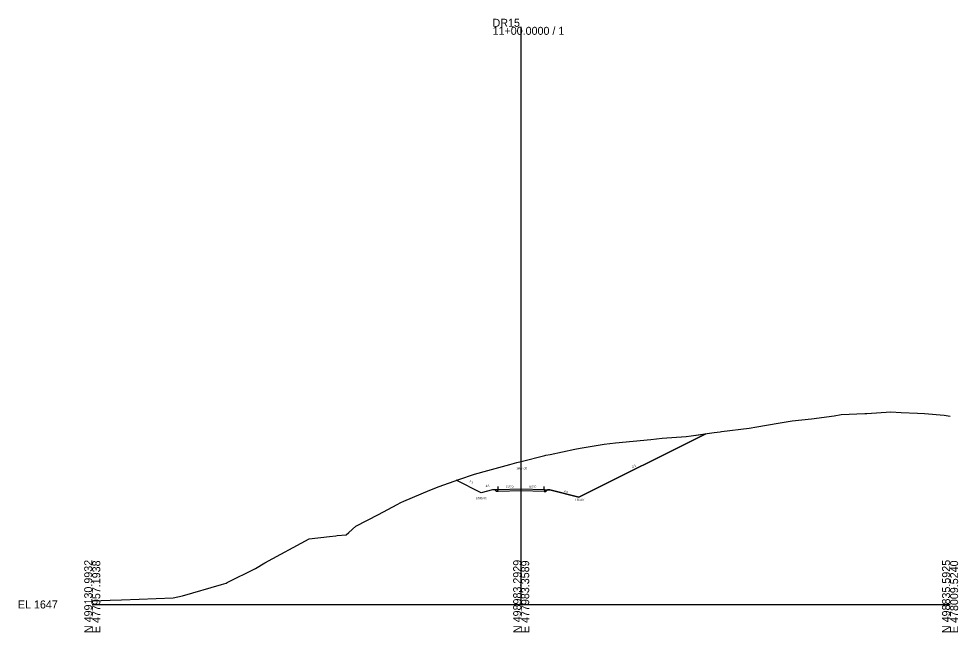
# Model space of a CAD drawing. Extents: x -26 to 303, y -10 to 4126.
# Drawn here: x -25.7 to 302.8, y 990.3 to 1204.8 of the extents above; entities that cross this region are included whole.
import ezdxf

# ---------------------------------------------------------------- set-up
doc = ezdxf.new("R2010")
doc.units = 0
for name, color, linetype in [('Exist Cross Section Cell', 7, 'Continuous'), ('Exist XS Center Line Elevation Label', 7, 'Continuous'), ('Exist XS Ground Line', 7, 'Continuous'), ('Prop Road Sect_ Boring - Material (Outline)', 7, 'Continuous'), ('Prop XS Ditch Slope Text', 7, 'Continuous'), ('Prop XS Ditch Standard Text', 7, 'Continuous'), ('Prop XS Earthwork Shape', 7, 'Continuous'), ('Prop XS EOT Tick Mark', 7, 'Continuous'), ('Prop XS Finish Grade', 7, 'Continuous'), ('Prop XS Finish Grade Earthwork', 7, 'Continuous'), ('Prop XS Finish Grade Pavement', 7, 'Continuous'), ('Prop XS Pvmt Edge Slope', 7, 'Continuous'), ('Prop XS SE Text', 7, 'Continuous'), ('Prop XS Side Slope Text', 7, 'Continuous'), ('Prop XS Subgrade Earthwork', 7, 'Continuous')]:
    doc.layers.add(name, color=color, linetype=linetype)

msp = doc.modelspace()

# ---------------------------------------------------------------- linework, layer by layer
at = {"layer": 'Exist Cross Section Cell'}
for p, q in [((150, 1000), (150, 1201.97)), ((0, 1000), (150, 1000)), ((150, 1000), (300, 1000))]:
    msp.add_line(p, q, dxfattribs=at)
at = {"layer": 'Exist XS Ground Line'}
msp.add_lwpolyline([(0, 1001.28), (6.28, 1001.54), (10.19, 1001.65), (16.43, 1001.82), (28.25, 1002.32), (31.6, 1003.03), (45.25, 1007.03), (46.87, 1007.47), (47.22, 1007.66), (57.07, 1012.59), (60.3, 1014.59), (75.81, 1022.96), (83.02, 1023.81), (85.17, 1024.03), (85.7, 1024.09), (88.74, 1024.37), (89.78, 1025.16), (92.2, 1027.36), (100.05, 1031.47), (106.67, 1035), (107.86, 1035.68), (108.95, 1036.14), (118.02, 1039.99), (121.29, 1041.22), (128.18, 1043.73), (133.64, 1045.54), (138.33, 1046.88), (145.98, 1048.97), (148.49, 1049.63), (150, 1050), (158.32, 1052.08), (158.65, 1052.15), (160.16, 1052.46), (168.81, 1054.28), (170.67, 1054.63), (178.97, 1056.03), (183.01, 1056.46), (189.12, 1057.08), (195.36, 1057.68), (199.28, 1058.1), (207.7, 1058.73), (209.44, 1058.98), (217.5, 1060.1), (219.6, 1060.39), (220.05, 1060.43), (229.75, 1061.7), (232.39, 1062.08), (239.91, 1063.45), (244.74, 1064.17), (251.54, 1064.86), (259.44, 1065.99), (261.91, 1066.41), (270.22, 1066.79), (270.94, 1066.79), (279.22, 1067.32), (282.92, 1067.15), (288.59, 1066.94), (291.09, 1066.74), (297.87, 1066.14), (300, 1065.84)], dxfattribs=at)
at = {"layer": 'Prop Road Sect_ Boring - Material (Outline)'}
for points in [[(142, 1040.22), (140.74, 1040.11), (141.32, 1039.54)], [(158, 1040.22), (159.26, 1040.11), (158.68, 1039.54)]]:
    msp.add_lwpolyline(points, close=True, dxfattribs=at)
at = {"layer": 'Prop XS Earthwork Shape'}
msp.add_lwpolyline([(127.29, 1043.41), (128.18, 1043.73), (133.64, 1045.54), (138.33, 1046.88), (145.98, 1048.97), (148.49, 1049.63), (150, 1050), (158.32, 1052.08), (158.65, 1052.15), (160.16, 1052.46), (168.81, 1054.28), (170.67, 1054.63), (178.97, 1056.03), (183.01, 1056.46), (189.12, 1057.08), (195.36, 1057.68), (199.28, 1058.1), (207.7, 1058.73), (209.44, 1058.98), (214.53, 1059.68), (170.18, 1037.51), (160, 1040.06), (159.26, 1040.11), (158.68, 1039.54), (158, 1039.55), (150, 1039.71), (142, 1039.55), (141.32, 1039.54), (140.74, 1040.11), (140, 1040.06), (136, 1039.06)], close=True, dxfattribs=at)
at = {"layer": 'Prop XS EOT Tick Mark'}
for p, q in [((142, 1040.22), (142, 1041.22)), ((158, 1040.22), (158, 1041.22))]:
    msp.add_line(p, q, dxfattribs=at)
at = {"layer": 'Prop XS Finish Grade'}
for p, q in [((142, 1040.22), (140.74, 1040.11)), ((158, 1040.22), (159.26, 1040.11))]:
    msp.add_line(p, q, dxfattribs=at)
at = {"layer": 'Prop XS Finish Grade Earthwork'}
for p, q in [((170.18, 1037.51), (214.53, 1059.68)), ((136, 1039.06), (127.29, 1043.41)), ((140, 1040.06), (136, 1039.06)), ((140.74, 1040.11), (140, 1040.06)), ((159.26, 1040.11), (160, 1040.06)), ((160, 1040.06), (170.18, 1037.51))]:
    msp.add_line(p, q, dxfattribs=at)
at = {"layer": 'Prop XS Finish Grade Pavement'}
for p, q in [((142, 1040.22), (150, 1040.38)), ((150, 1040.38), (158, 1040.22))]:
    msp.add_line(p, q, dxfattribs=at)
at = {"layer": 'Prop XS Pvmt Edge Slope'}
for p, q in [((142, 1040.22), (141.32, 1039.54)), ((158, 1040.22), (158.68, 1039.54))]:
    msp.add_line(p, q, dxfattribs=at)
at = {"layer": 'Prop XS Subgrade Earthwork'}
for p, q in [((141.32, 1039.54), (140.74, 1040.11)), ((142, 1039.55), (141.32, 1039.54)), ((150, 1039.71), (142, 1039.55)), ((158, 1039.55), (150, 1039.71)), ((158, 1039.55), (158.68, 1039.54)), ((158.68, 1039.54), (159.26, 1040.11))]:
    msp.add_line(p, q, dxfattribs=at)

# ---------------------------------------------------------------- texts
at = {"layer": 'Exist Cross Section Cell'}
for s, p in [('DR15', (140, 1201.97)), ('11+00.0000 / 1', (140, 1199.17)), ('EL 1647', (-26, 998.6))]:
    msp.add_text(s, height=2.8, dxfattribs=at).set_placement(p)
for s, p in [('N 499130.9932', (0, 990)), ('E 477957.1938', (2.8, 990)), ('N 498983.2929', (150, 990)), ('E 477983.3589', (152.8, 990)), ('N 498835.5925', (300, 990)), ('E 478009.5240', (302.8, 990))]:
    msp.add_text(s, height=2.8, rotation=90, dxfattribs=at).set_placement(p)
at = {"layer": 'Exist XS Center Line Elevation Label'}
msp.add_text('1697.00', height=0.75, dxfattribs=at).set_placement((148.29, 1047.25))
at = {"layer": 'Prop XS Ditch Slope Text'}
for rotation, p in [(14.0362, (137.64, 1041.01)), (345.9638, (164.87, 1039.28))]:
    msp.add_text('4:1', height=0.75, rotation=rotation, dxfattribs=at).set_placement(p)
at = {"layer": 'Prop XS Ditch Standard Text'}
for s, p in [('1686.06', (134.19, 1036.81)), ('1684.51', (168.85, 1036.27))]:
    msp.add_text(s, height=0.75, dxfattribs=at).set_placement(p)
at = {"layer": 'Prop XS SE Text'}
for rotation, p in [(1.1458, (144.69, 1040.77)), (358.8542, (152.69, 1040.82))]:
    msp.add_text('0.020', height=0.75, rotation=rotation, dxfattribs=at).set_placement(p)
at = {"layer": 'Prop XS Side Slope Text'}
for rotation, p in [(26.5651, (188.97, 1047.71)), (333.4349, (131.78, 1042.84))]:
    msp.add_text('2:1', height=0.75, rotation=rotation, dxfattribs=at).set_placement(p)

doc.saveas('drawing.dxf')
